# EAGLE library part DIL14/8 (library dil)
SOCKET Dual In Line, 8 pins used
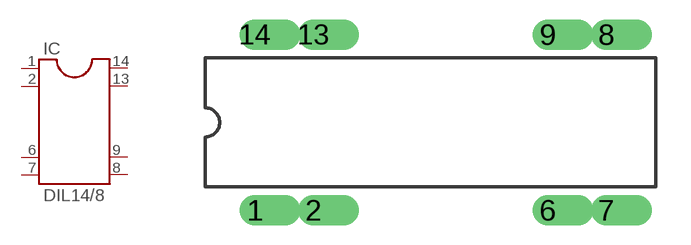
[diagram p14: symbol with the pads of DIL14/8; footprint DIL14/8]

Designator prefix IC

## DIL14/8  [DIL14/8]
1  1  pas
2  2  pas
6  6  pas
7  7  pas
8  8  pas
9  9  pas
13  13  pas
14  14  pas

## Footprint DIL14/8 (pad centres in mm)
SOCKET Dual In Line, 8 pins used
drill 0.813 offset: 1 -7.62,-3.81; 2 -5.08,-3.81; 6 5.08,-3.81; 7 7.62,-3.81; 8 7.62,3.81; 9 5.08,3.81; 13 -5.08,3.81; 14 -7.62,3.81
